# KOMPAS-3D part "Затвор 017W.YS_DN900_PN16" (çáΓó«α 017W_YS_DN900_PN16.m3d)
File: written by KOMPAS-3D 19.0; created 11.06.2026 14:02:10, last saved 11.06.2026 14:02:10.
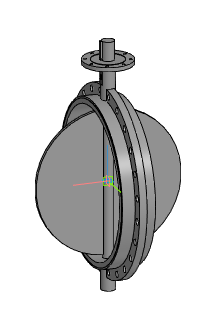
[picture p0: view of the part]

Document properties: Автор: Евгений; Полное имя файла: Z:\3.Личные\kachalov\001_3d для проектировщиков\x.x Тип 017W.Y(S) Затвор дисковый поворотный межфланцевый\_stp_Затвор 017W.YS_DN32-DN1200\Затвор 017W_YS_DN900_PN16.m3d

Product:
- Part/product: Затвор 017W.YS_DN900_PN16

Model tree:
1. Операция без истории:1  (labels: Затвор 017W.YS_DN900_PN16)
